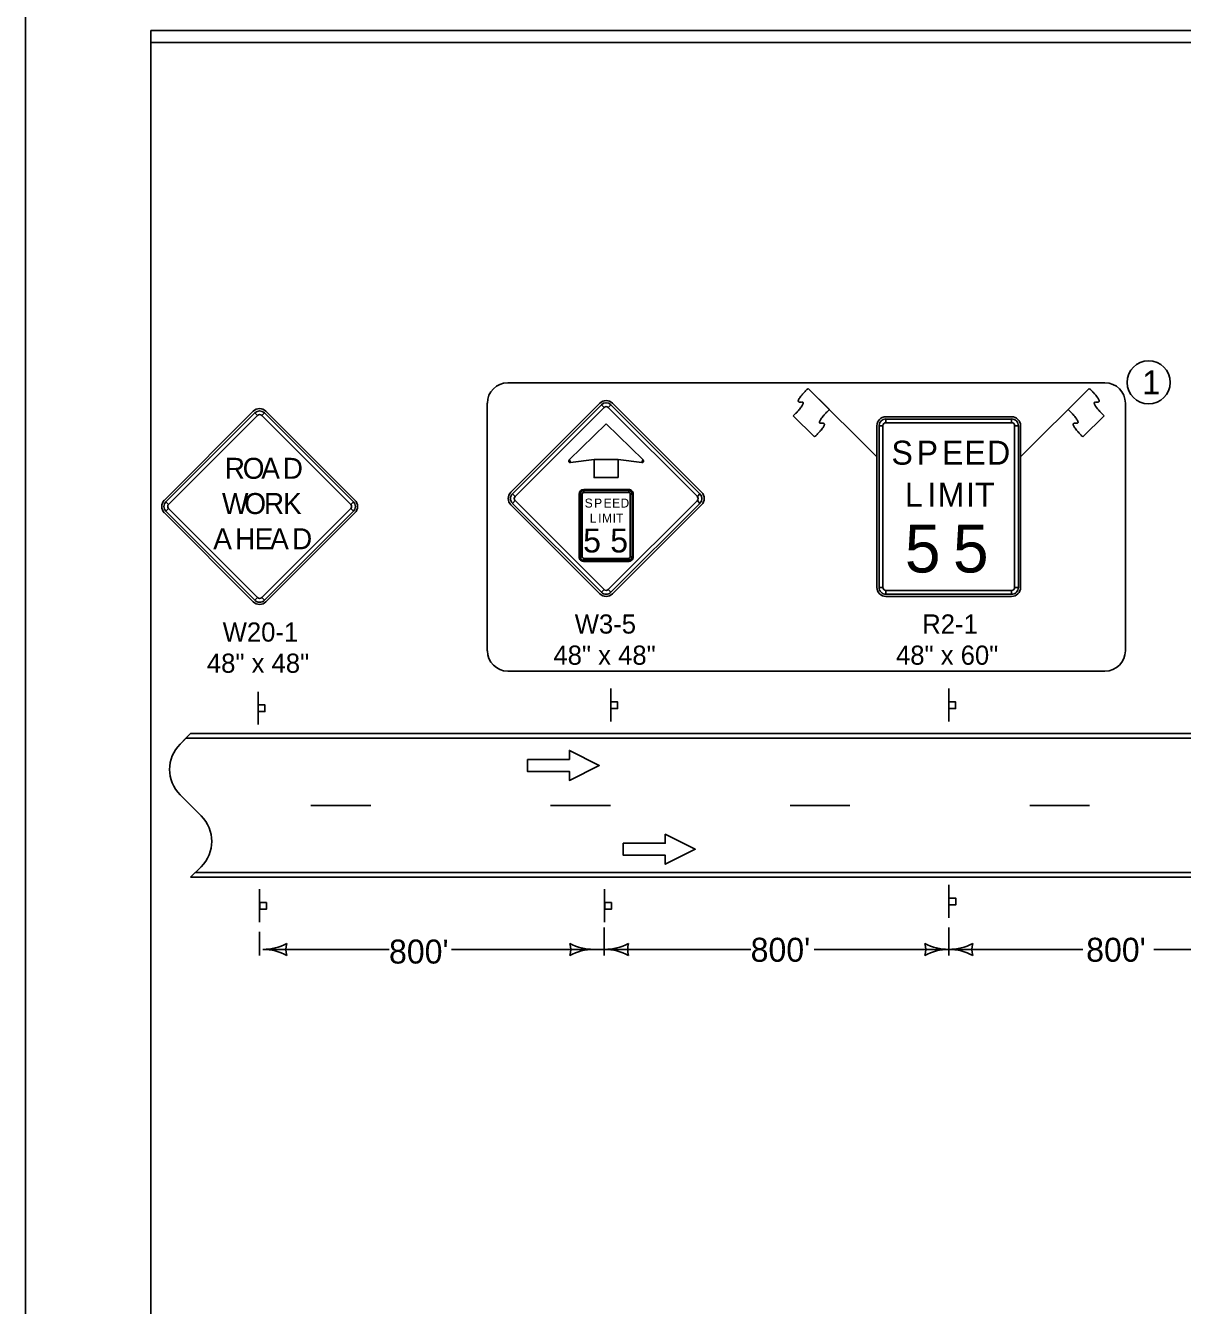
# Model space of a CAD drawing. Extents: x 10133 to 81668, y 4177 to 11018.
# Drawn here: x 28028 to 28993, y 8880 to 9948 of the extents above; entities that cross this region are included whole.
import ezdxf

# ---------------------------------------------------------------- set-up
doc = ezdxf.new("R2010")
doc.units = 0
for name, color, linetype in [('dsnNonPlotable', 7, 'Continuous'), ('dsnStdBlockModified', 7, 'Continuous'), ('dsnStdBorder', 7, 'Continuous'), ('dsnStdDimension', 7, 'Continuous'), ('dsnStdLabel', 7, 'Continuous'), ('dsnStdNote', 7, 'Continuous'), ('Level 2', 7, 'Continuous'), ('SheetBorder', 7, 'Continuous')]:
    doc.layers.add(name, color=color, linetype=linetype)

msp = doc.modelspace()

# ---------------------------------------------------------------- linework, layer by layer
at = {"layer": 'dsnNonPlotable'}
for p, q in [((28738.4, 9587.9), (28681.1, 9645.2)), ((28681.1, 9645.2), (28698.8, 9627.6)), ((28858.4, 9587.9), (28915.7, 9645.2)), ((28915.7, 9645.2), (28898.1, 9627.6)), ((28218, 9626.1), (28143.8, 9551.9)), ((28219.4, 9624.8), (28221.6, 9622.6)), ((28225.1, 9622.6), (28227.3, 9624.8)), ((28302.9, 9551.9), (28228.6, 9626.1)), ((28507.2, 9632.8), (28433, 9558.5)), ((28508.6, 9631.4), (28510.8, 9629.2)), ((28514.3, 9629.2), (28516.5, 9631.4)), ((28592.1, 9558.5), (28517.8, 9632.8)), ((28668.7, 9622.2), (28686.4, 9604.6)), ((28686.4, 9604.6), (28668.7, 9622.2)), ((28738.4, 9614), (28738.4, 9479)), ((28740.3, 9614), (28743.4, 9614)), ((28850.9, 9621.5), (28745.9, 9621.5)), ((28745.9, 9616.5), (28745.9, 9619.6)), ((28850.9, 9619.6), (28850.9, 9616.5)), ((28853.4, 9614), (28856.5, 9614)), ((28858.4, 9479), (28858.4, 9614)), ((28928.1, 9622.2), (28910.4, 9604.6)), ((28910.4, 9604.6), (28928.1, 9622.2)), ((28482.5, 9584.5), (28481.7, 9585.4)), ((28482.7, 9583.2), (28482.5, 9584.5)), ((28542.5, 9584.5), (28542.4, 9583.2)), ((28543.4, 9585.4), (28542.5, 9584.5)), ((28531.3, 9560.7), (28493.8, 9560.7)), ((28147.3, 9548.3), (28145.1, 9550.5)), ((28301.6, 9550.5), (28299.4, 9548.3)), ((28436.5, 9555), (28434.3, 9557.2)), ((28434.3, 9549.2), (28436.5, 9551.5)), ((28490, 9557), (28490, 9504.5)), ((28491, 9557), (28492.5, 9557)), ((28493.8, 9558.2), (28493.8, 9559.8)), ((28531.3, 9559.8), (28531.3, 9558.2)), ((28532.5, 9557), (28534.1, 9557)), ((28535, 9504.5), (28535, 9557)), ((28590.8, 9557.2), (28588.6, 9555)), ((28588.6, 9551.5), (28590.8, 9549.2)), ((28143.8, 9541.3), (28218, 9467)), ((28145.1, 9542.6), (28147.3, 9544.8)), ((28228.6, 9467), (28302.9, 9541.3)), ((28299.4, 9544.8), (28301.6, 9542.6)), ((28433, 9547.9), (28507.2, 9473.7)), ((28517.8, 9473.7), (28592.1, 9547.9)), ((28492.5, 9504.5), (28491, 9504.5)), ((28493.8, 9501.7), (28493.8, 9503.2)), ((28493.8, 9500.7), (28531.3, 9500.7)), ((28531.3, 9503.2), (28531.3, 9501.7)), ((28534.1, 9504.5), (28532.5, 9504.5)), ((28510.8, 9477.2), (28508.6, 9475)), ((28516.5, 9475), (28514.3, 9477.2)), ((28743.4, 9479), (28740.3, 9479)), ((28745.9, 9473.3), (28745.9, 9476.5)), ((28850.9, 9476.5), (28850.9, 9473.3)), ((28856.5, 9479), (28853.4, 9479)), ((28221.6, 9470.6), (28219.4, 9468.3)), ((28227.3, 9468.3), (28225.1, 9470.6)), ((28745.9, 9471.5), (28850.9, 9471.5)), ((28222.1, 9364.5), (28222.1, 9392)), ((28516.3, 9367.1), (28516.3, 9394.6)), ((28798.4, 9367.1), (28798.4, 9394.6)), ((28798.4, 9203.3), (28798.4, 9230.8)), ((28223.3, 9199.6), (28223.3, 9227.1)), ((28511.2, 9199.6), (28511.2, 9227.1))]:
    msp.add_line(p, q, dxfattribs=at)
for points in [[(28430.4, 9649.9), (28928.8, 9649.9)], [(28413.3, 9426.2), (28413.3, 9632.8)], [(28945.8, 9632.8), (28945.8, 9426.2)], [(28928.8, 9409.2), (28430.4, 9409.2)], [(28446.8, 9335.5), (28446.8, 9325.5), (28481.8, 9325.5), (28481.8, 9318), (28506.8, 9330.5), (28481.8, 9343), (28481.8, 9335.5), (28446.8, 9335.5)], [(28526.8, 9265.5), (28526.8, 9255.5), (28561.8, 9255.5), (28561.8, 9248), (28586.8, 9260.5), (28561.8, 9273), (28561.8, 9265.5), (28526.8, 9265.5)]]:
    msp.add_lwpolyline(points, dxfattribs=at)
for points in [[(28219.4, 9624.8), (28145.1, 9550.5), (28147.3, 9548.3), (28221.6, 9622.6), (28219.4, 9624.8)], [(28301.6, 9550.5), (28227.3, 9624.8), (28225.1, 9622.6), (28299.4, 9548.3), (28301.6, 9550.5)], [(28508.6, 9631.4), (28434.3, 9557.2), (28436.5, 9555), (28510.8, 9629.2), (28508.6, 9631.4)], [(28590.8, 9557.2), (28516.5, 9631.4), (28514.3, 9629.2), (28588.6, 9555), (28590.8, 9557.2)], [(28512.5, 9615.7), (28481.7, 9585.4), (28482.5, 9584.5), (28482.7, 9583.2), (28502.5, 9585.7), (28522.5, 9585.7), (28542.4, 9583.2), (28542.5, 9584.5), (28543.4, 9585.4), (28512.5, 9615.7)], [(28740.3, 9614), (28740.3, 9479), (28743.4, 9479), (28743.4, 9614), (28740.3, 9614)], [(28850.9, 9619.6), (28745.9, 9619.6), (28745.9, 9616.5), (28850.9, 9616.5), (28850.9, 9619.6)], [(28856.5, 9479), (28856.5, 9614), (28853.4, 9614), (28853.4, 9479), (28856.5, 9479)], [(28522.5, 9570.7), (28502.5, 9570.7), (28502.5, 9585.7), (28522.5, 9585.7), (28522.5, 9570.7)], [(28434.3, 9549.2), (28508.6, 9475), (28510.8, 9477.2), (28436.5, 9551.5), (28434.3, 9549.2)], [(28491, 9557), (28491, 9504.5), (28492.5, 9504.5), (28492.5, 9557), (28491, 9557)], [(28531.3, 9559.8), (28493.8, 9559.8), (28493.8, 9558.2), (28531.3, 9558.2), (28531.3, 9559.8)], [(28516.5, 9475), (28590.8, 9549.2), (28588.6, 9551.5), (28514.3, 9477.2), (28516.5, 9475)], [(28534.1, 9504.5), (28534.1, 9557), (28532.5, 9557), (28532.5, 9504.5), (28534.1, 9504.5)], [(28145.1, 9542.6), (28219.4, 9468.3), (28221.6, 9470.6), (28147.3, 9544.8), (28145.1, 9542.6)], [(28227.3, 9468.3), (28301.6, 9542.6), (28299.4, 9544.8), (28225.1, 9470.6), (28227.3, 9468.3)], [(28493.8, 9501.7), (28531.3, 9501.7), (28531.3, 9503.2), (28493.8, 9503.2), (28493.8, 9501.7)], [(28745.9, 9473.3), (28850.9, 9473.3), (28850.9, 9476.5), (28745.9, 9476.5), (28745.9, 9473.3)], [(28222.2, 9381), (28222.2, 9375.4), (28227.8, 9375.4), (28227.8, 9381)], [(28516.4, 9383.5), (28516.4, 9377.9), (28522.1, 9377.9), (28522.1, 9383.5)], [(28798.5, 9383.5), (28798.5, 9377.9), (28804.1, 9377.9), (28804.1, 9383.5)], [(28798.5, 9219.7), (28798.5, 9214.1), (28804.2, 9214.1), (28804.2, 9219.7)], [(28223.4, 9216), (28223.4, 9210.4), (28229, 9210.4), (28229, 9216)], [(28511.3, 9216), (28511.3, 9210.4), (28516.9, 9210.4), (28516.9, 9216)]]:
    msp.add_lwpolyline(points, close=True, dxfattribs=at)
for centre, radius, start, end in [((28430.4, 9632.8), 17, 90, 180), ((28928.8, 9632.8), 17, 0, 90), ((28223.3, 9620.8), 7.5, 45, 134.9997), ((28223.3, 9620.8), 5.62, 45, 134.9997), ((28512.5, 9627.5), 7.5, 45, 134.9997), ((28512.5, 9627.5), 5.62, 45, 134.9997), ((28512.5, 9627.5), 2.5, 45, 134.9997), ((28223.3, 9620.8), 2.5, 45, 134.9997), ((28745.9, 9614), 7.5, 90.0002, 179.9998), ((28745.9, 9614), 5.62, 90.0002, 179.9998), ((28745.9, 9614), 2.5, 90.0002, 179.9998), ((28850.9, 9614), 7.5, 0, 90.0002), ((28850.9, 9614), 5.62, 0, 90.0002), ((28850.9, 9614), 2.5, 0, 90.0002), ((28482.5, 9584.5), 1.25, 134.9997, 277.1529), ((28542.5, 9584.5), 1.25, 262.8473, 44.9998), ((28493.8, 9557), 3.75, 90.0002, 179.9998), ((28531.3, 9557), 3.75, 0, 90.0002), ((28149.1, 9546.6), 7.5, 134.9997, 225), ((28149.1, 9546.6), 5.62, 134.9997, 225), ((28297.6, 9546.6), 5.62, 315.0002, 44.9998), ((28297.6, 9546.6), 7.5, 315.0002, 44.9998), ((28438.3, 9553.2), 7.5, 134.9997, 225), ((28438.3, 9553.2), 5.62, 134.9997, 225), ((28438.3, 9553.2), 2.5, 134.9997, 225), ((28493.8, 9557), 2.81, 90.0002, 179.9998), ((28493.8, 9557), 1.25, 90.0002, 179.9998), ((28531.3, 9557), 2.81, 0, 90.0002), ((28531.3, 9557), 1.25, 0, 90.0002), ((28586.8, 9553.2), 2.5, 315.0002, 44.9998), ((28586.8, 9553.2), 5.62, 315.0002, 44.9998), ((28586.8, 9553.2), 7.5, 315.0002, 44.9998), ((28149.1, 9546.6), 2.5, 134.9997, 225), ((28297.6, 9546.6), 2.5, 315.0002, 44.9998), ((28493.8, 9504.5), 3.75, 179.9998, 270.0001), ((28493.8, 9504.5), 2.81, 179.9998, 270.0001), ((28493.8, 9504.5), 1.25, 179.9998, 270.0001), ((28531.3, 9504.5), 3.75, 270.0001, 0.0003), ((28531.3, 9504.5), 2.81, 270.0001, 0.0003), ((28531.3, 9504.5), 1.25, 270.0001, 0.0003), ((28512.5, 9479), 2.5, 225, 315.0002), ((28745.9, 9479), 7.5, 179.9998, 270.0001), ((28745.9, 9479), 5.62, 179.9998, 270.0001), ((28745.9, 9479), 2.5, 179.9998, 270.0001), ((28850.9, 9479), 7.5, 270.0001, 0.0003), ((28850.9, 9479), 5.62, 270.0001, 0.0003), ((28850.9, 9479), 2.5, 270.0001, 0.0003), ((28223.3, 9472.3), 7.5, 225, 315.0002), ((28223.3, 9472.3), 5.62, 225, 315.0002), ((28223.3, 9472.3), 2.5, 225, 315.0002), ((28512.5, 9479), 7.5, 225, 315.0002), ((28512.5, 9479), 5.62, 225, 315.0002), ((28430.4, 9426.2), 17, 180, 270), ((28928.8, 9426.2), 17, 270, 0)]:
    msp.add_arc(centre, radius, start, end, dxfattribs=at)
for points in [[(28681.1, 9645.2), (28668.7, 9632.9), (28681.1, 9634.6), (28668.7, 9622.2)], [(28668.7, 9622.2), (28681.1, 9634.6), (28668.7, 9632.9), (28681.1, 9645.2)], [(28915.7, 9645.2), (28928.1, 9632.9), (28915.7, 9634.6), (28928.1, 9622.2)], [(28928.1, 9622.2), (28915.7, 9634.6), (28928.1, 9632.9), (28915.7, 9645.2)], [(28698.8, 9627.6), (28686.4, 9615.2), (28698.8, 9616.9), (28686.4, 9604.6)], [(28698.8, 9627.6), (28686.4, 9615.2), (28698.8, 9616.9), (28686.4, 9604.6)], [(28898.1, 9627.6), (28910.4, 9615.2), (28898.1, 9616.9), (28910.4, 9604.6)], [(28898.1, 9627.6), (28910.4, 9615.2), (28898.1, 9616.9), (28910.4, 9604.6)]]:
    msp.add_open_spline(points, degree=2, dxfattribs=at)
at = {"layer": 'dsnStdBlockModified'}
msp.add_lwpolyline([(28132.5, 9934), (31267.5, 9934), (31267.5, 7924), (28132.5, 7924)], close=True, dxfattribs=at)
at = {"layer": 'dsnStdBorder'}
msp.add_lwpolyline([(28028, 7819.5), (31372, 7819.5), (31372, 10403.5), (28028, 10403.5)], close=True, dxfattribs=at)
at = {"layer": 'dsnStdDimension'}
for p, q in [((28157, 9348.3), (28161.7, 9353.1)), ((28165.7, 9357.1), (28161.7, 9353.1)), ((28161.7, 9353.1), (29379, 9353.1)), ((28161.7, 9353.1), (29957.3, 9353.1)), ((28165.7, 9357.1), (30292.4, 9357.1)), ((29955.6, 9357.1), (28165.7, 9357.1)), ((28174.5, 9288.3), (28157, 9305.9)), ((28165.7, 9237.1), (28174.5, 9245.9)), ((28165.7, 9237.1), (30497.9, 9237.1)), ((29210.2, 9237.1), (28165.7, 9237.1))]:
    msp.add_line(p, q, dxfattribs=at)
msp.add_lwpolyline([(28161.7, 9353.1), (28161.7, 9353.1)], dxfattribs=at)
msp.add_lwpolyline([(28161.7, 9353.1), (28161.7, 9353.1)], dxfattribs=at)
for centre, start, end in [((28178.2, 9327.1), 135, 225), ((28153.3, 9267.1), 315, 45)]:
    msp.add_arc(centre, 30, start, end, dxfattribs=at)
at = {"layer": 'dsnStdLabel'}
for p, q in [((28165.7, 9357.1), (28157, 9348.3)), ((28157, 9305.8), (28174.5, 9288.3)), ((28174.5, 9245.9), (28165.7, 9237.1)), ((28169.7, 9241.1), (29785, 9241.1))]:
    msp.add_line(p, q, dxfattribs=at)
for points in [[(28161.7, 9353.1), (30191.3, 9353.1)], [(28266.1, 9297), (28316.1, 9297)], [(28466.1, 9297), (28516.1, 9297)], [(28666.1, 9297), (28716, 9297)], [(28866, 9297), (28916, 9297)]]:
    msp.add_lwpolyline(points, dxfattribs=at)
for centre, start, end in [((28178.2, 9327.1), 135, 225), ((28153.3, 9267.1), 315, 45)]:
    msp.add_arc(centre, 30, start, end, dxfattribs=at)
at = {"layer": 'dsnStdNote'}
for p, q in [((28223.3, 9191.6), (28223.3, 9171.8)), ((28510.8, 9195.3), (28510.8, 9171.8)), ((28798.4, 9195.3), (28798.4, 9171.8)), ((28798.4, 9191.6), (28798.4, 9171.8)), ((28331.5, 9176.9), (28226.1, 9176.9)), ((28383.4, 9176.9), (28510.8, 9176.9)), ((28633.3, 9176.9), (28510.8, 9176.9)), ((28686, 9176.9), (28798.4, 9176.9)), ((28910.2, 9176.9), (28798.4, 9176.9)), ((28969.6, 9176.9), (29086, 9176.9))]:
    msp.add_line(p, q, dxfattribs=at)
for centre, radius, start, end in [((28226.1, 9219.4), 42.5, 270, 298.0725), ((28226.1, 9134.4), 42.5, 61.9275, 90), ((28261.7, 9176.9), 16.4, 162.2666, 197.7334), ((28466.5, 9176.9), 16.4, 342.2667, 17.7334), ((28502.1, 9219.4), 42.5, 241.9275, 270), ((28502.1, 9134.4), 42.5, 90, 118.0725), ((28511.2, 9219.4), 42.5, 270, 298.0725), ((28511.2, 9134.4), 42.5, 61.9275, 90), ((28546.9, 9176.9), 16.4, 162.2666, 197.7334), ((28762.8, 9176.9), 16.4, 342.2667, 17.7334), ((28798.4, 9219.4), 42.5, 241.9275, 270), ((28798.4, 9134.4), 42.5, 90, 118.0725), ((28798.4, 9219.4), 42.5, 270, 298.0725), ((28798.4, 9134.4), 42.5, 61.9275, 90), ((28834.1, 9176.9), 16.4, 162.2666, 197.7334)]:
    msp.add_arc(centre, radius, start, end, dxfattribs=at)
at = {"layer": 'Level 2'}
msp.add_circle((28965.2, 9650.2), 18, dxfattribs=at)
at = {"layer": 'SheetBorder'}
msp.add_lwpolyline([(28132.5, 9944), (31267.5, 9944), (31267.5, 7924), (28132.5, 7924)], close=True, dxfattribs=at)

# ---------------------------------------------------------------- texts
at = {"layer": 'dsnNonPlotable'}
for s, height, p in [('S', 20, (28750.6, 9581.5)), ('P', 20, (28771.6, 9581.5)), ('E', 20, (28792.7, 9581.5)), ('E', 20, (28811.5, 9581.5)), ('D', 20, (28830.4, 9581.5)), ('R', 17.5, (28194.2, 9569.7)), ('O', 17.5, (28209.2, 9569.7)), ('A', 17.5, (28224.7, 9569.7)), ('D', 17.5, (28242.6, 9569.7)), ('L', 20, (28761.8, 9546.5)), ('I', 20, (28780.6, 9546.5)), ('M', 20, (28789.2, 9546.5)), ('I', 20, (28812.8, 9546.5)), ('T', 20, (28820.4, 9546.5)), ('W', 17.5, (28191.9, 9540.3)), ('O', 17.5, (28210.5, 9540.3)), ('R', 17.5, (28226.9, 9540.3)), ('K', 17.5, (28242.8, 9540.3)), ('S', 7.5, (28494.6, 9545.7)), ('P', 7.5, (28502.5, 9545.7)), ('E', 7.5, (28510.4, 9545.7)), ('E', 7.5, (28517.5, 9545.7)), ('D', 7.5, (28524.5, 9545.7)), ('L', 7.5, (28498.8, 9533.2)), ('I', 7.5, (28505.9, 9533.2)), ('M', 7.5, (28509.1, 9533.2)), ('I', 7.5, (28517.9, 9533.2)), ('T', 7.5, (28520.8, 9533.2)), ('5', 40, (28761.8, 9491.5)), ('5', 40, (28801.9, 9491.5)), ('A', 17.5, (28184.6, 9510.9)), ('H', 17.5, (28202.8, 9510.9)), ('E', 17.5, (28219.1, 9510.9)), ('A', 17.5, (28232.1, 9510.9)), ('D', 17.5, (28250.3, 9510.9)), ('5', 20, (28493.3, 9508.2)), ('5', 20, (28515.9, 9508.2)), ('W3-5', 16, (28486.3, 9440.5)), ('R2-1', 16, (28776.3, 9440.5)), ('W20-1', 16, (28192.5, 9433.8)), ('48" x 48"', 16, (28179.3, 9407.8)), ('48" x 48"', 16, (28468.5, 9414.5)), ('48" x 60"', 16, (28754.4, 9414.5))]:
    msp.add_text(s, height=height, dxfattribs=at).set_placement(p)
at = {"layer": 'dsnStdNote'}
for p in [(28633.1, 9166.6), (28913.1, 9166.6), (28331.3, 9165.1)]:
    msp.add_text("800'", height=20, dxfattribs=at).set_placement(p)
at = {"layer": 'Level 2'}
msp.add_text('1', height=20, dxfattribs=at).set_placement((28960, 9640.2))

doc.saveas('drawing.dxf')
